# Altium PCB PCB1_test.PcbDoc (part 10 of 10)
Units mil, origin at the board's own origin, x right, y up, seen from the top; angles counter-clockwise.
Board outline 6690 x 6690 mil, 6 copper layers (Layer 1 - Top Layer, Layer 2 - GND, Layer 3 - PWR, Layer 4 - Signal, Layer 5 - GND, Layer 6 - Bottom Layer), stack 80.244 mil thick; 821 components, 458 nets, 3752 pads, 1525 vias.
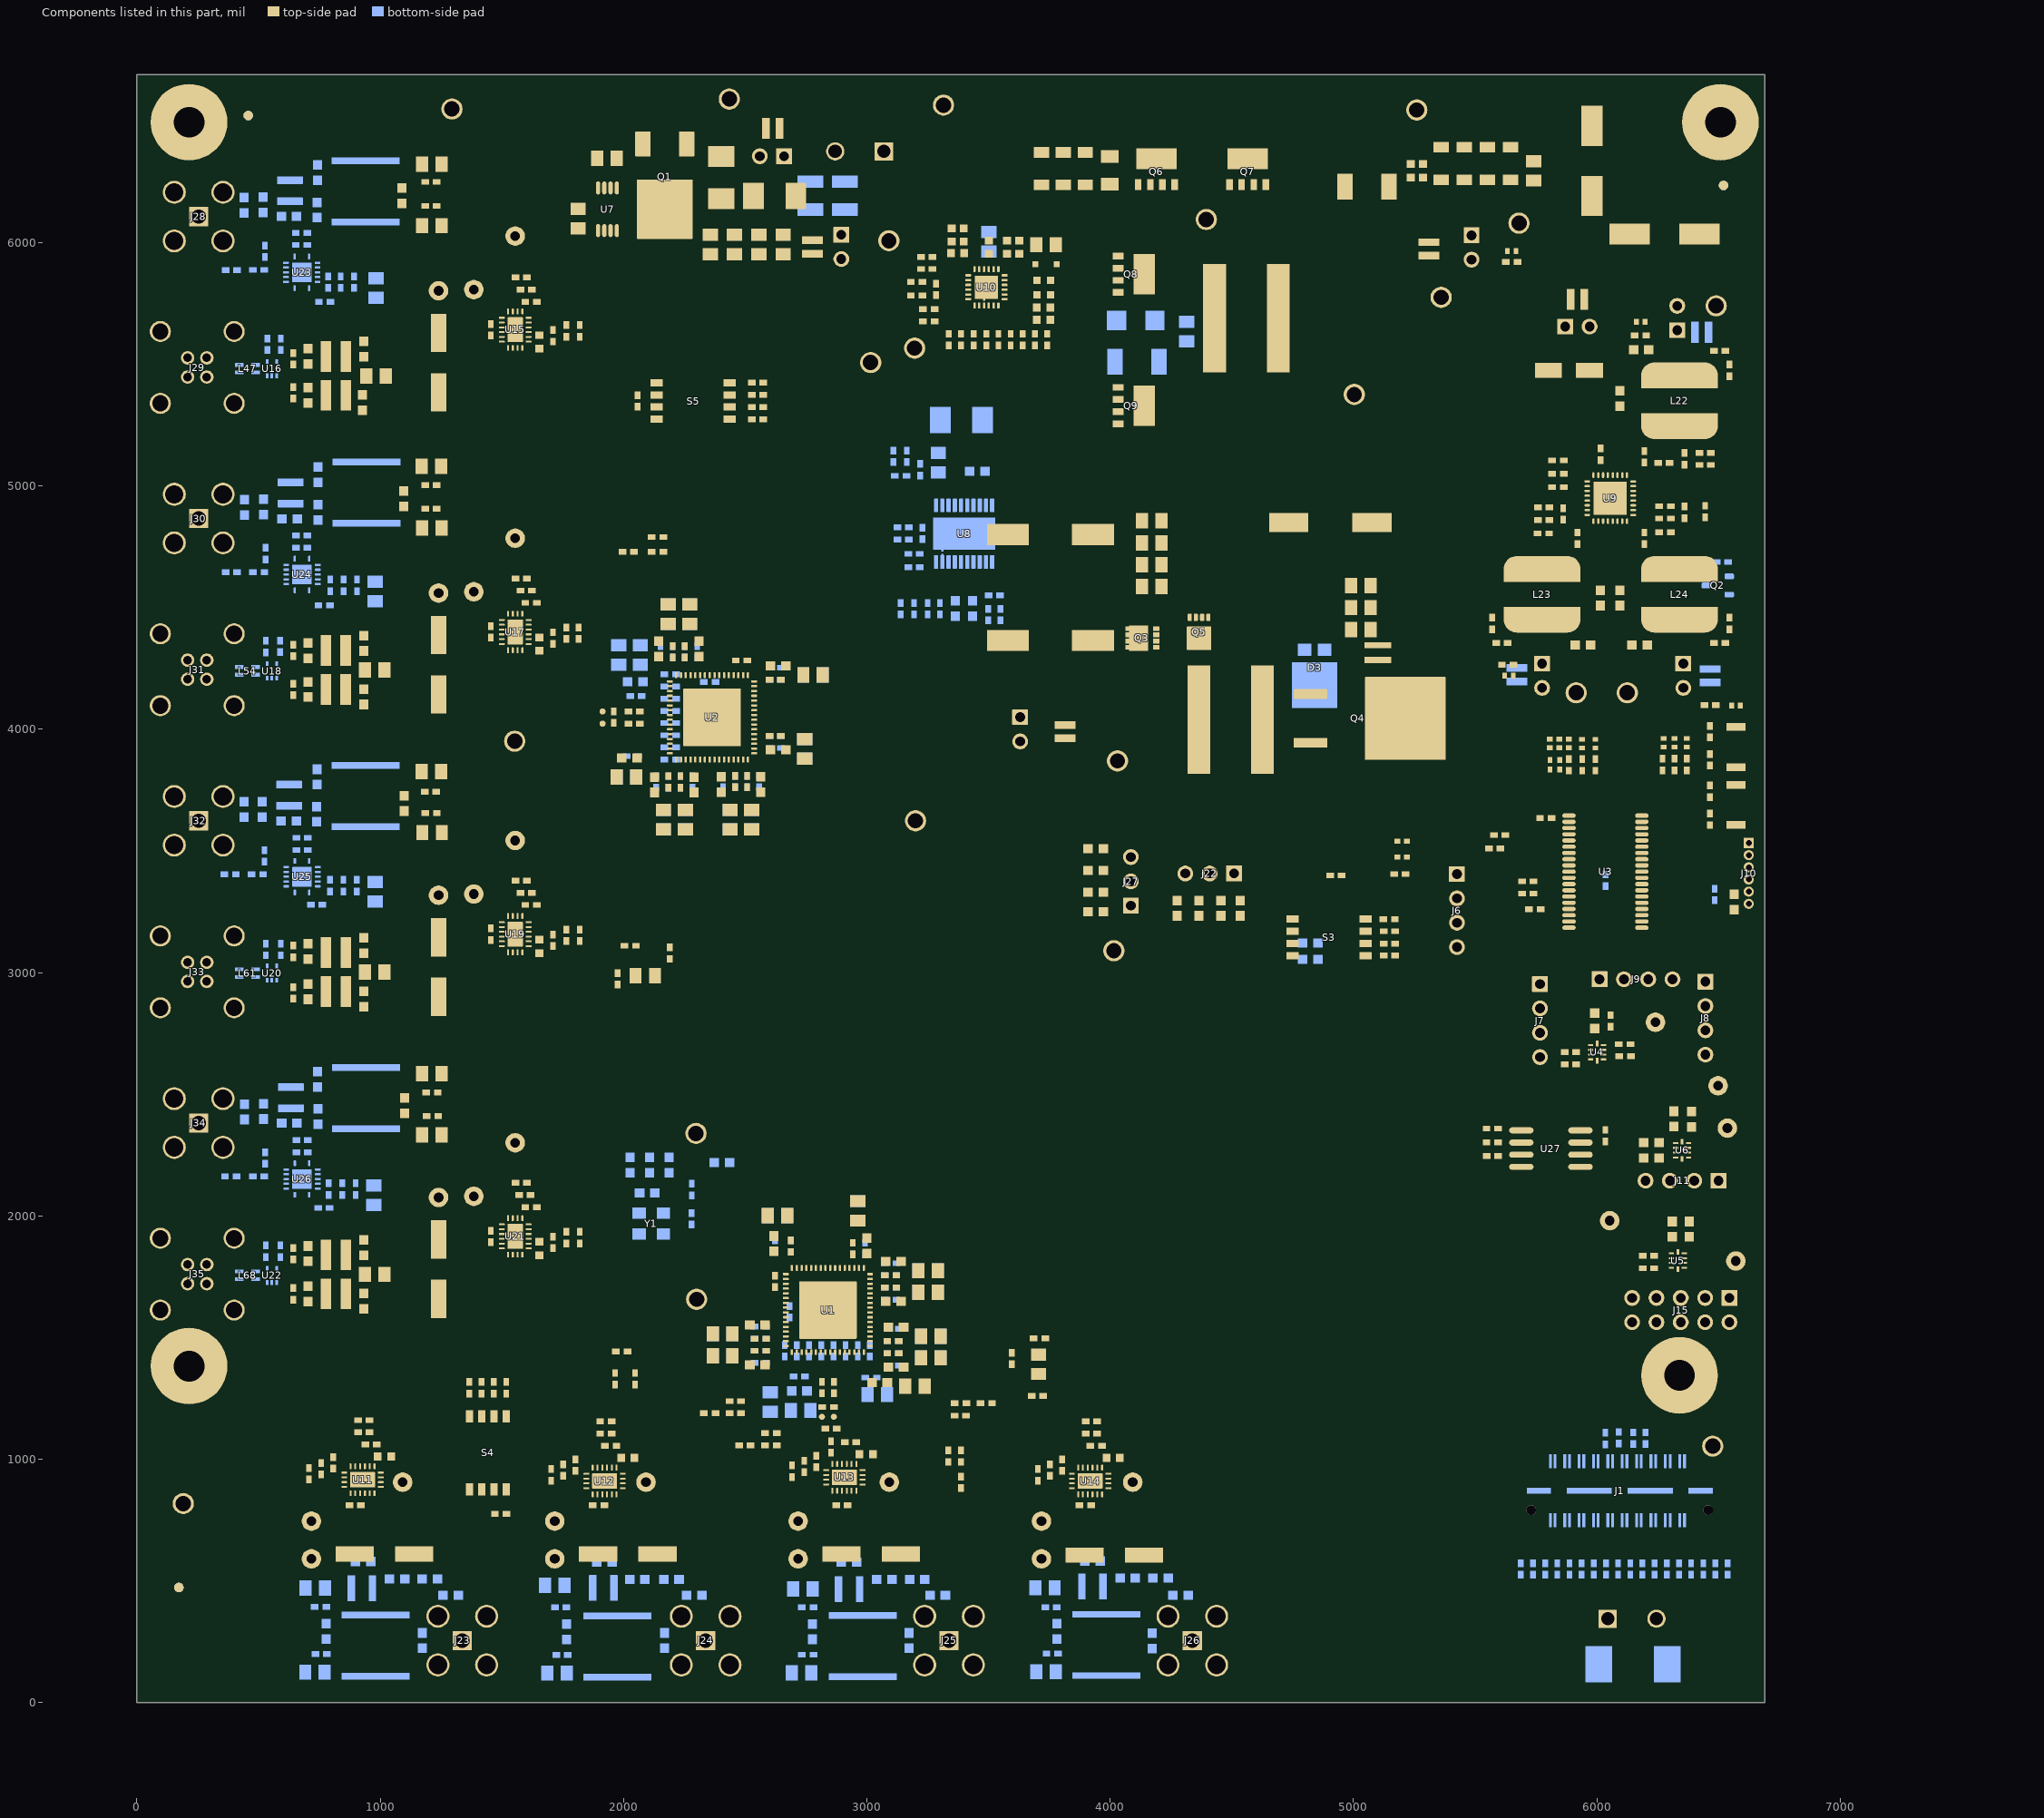
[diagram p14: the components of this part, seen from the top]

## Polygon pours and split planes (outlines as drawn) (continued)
NetR32_1 on Layer 6 - Bottom Layer "LAYER_6_-_BOTTOM_LAYER_NETR32_1_P303" (solid, remove dead copper, pour order 265): 2102.79,2069.09 2102.79,2139.09 2007.79,2139.09 2007.79,2199.09 2212.79,2199.09 2212.79,2139.09 2152.79,2139.09 2152.79,2069.09
AGND2 on Layer 6 - Bottom Layer "LAYER_6_-_BOTTOM_LAYER_AGND2_P251" (solid, remove dead copper, pour order 244): 3216,5179.48 3038.84,5179.48 3038.84,4472.24 3270.5,4472.24 3270.5,4734.48 3216,4734.48
GND on Layer 6 - Bottom Layer "LAYER_6_-_BOTTOM_LAYER_GND_P321" (solid, remove dead copper, pour order 274): 2654.09,1799.33 2654.09,1427.28 3026.14,1427.28 3026.14,1799.33
GND on Layer 6 - Bottom Layer "LAYER_6_-_BOTTOM_LAYER_GND_P323" (solid, remove dead copper, pour order 275): 2178.22,4233.86 2178.22,3861.81 2550.27,3861.81 2550.27,4233.86
GND on Layer 6 - Bottom Layer "LAYER_6_-_BOTTOM_LAYER_GND_P122" (solid, remove dead copper, pour order 195): 50,3787 50,3462 50,3352 400,3352 400,3787
GND on Layer 6 - Bottom Layer "LAYER_6_-_BOTTOM_LAYER_GND_P120" (solid, remove dead copper, pour order 194): 50,5029 50,4704 50,4594 400,4594 400,5029
GND on Layer 6 - Bottom Layer "LAYER_6_-_BOTTOM_LAYER_GND_P116" (solid, remove dead copper, pour order 193): 50,6270 50,5945 50,5835 400,5835 400,6270
GND on Layer 6 - Bottom Layer "Top Layer-No Net 1" (solid, remove dead copper, pour order 385): 31,35 4529.51,35 ccw(c4529.51,55.49) 4544,41 cw(c4558.49,55.49) 4538,55.49 4538,490.58 ccw(c4438,490.58) 4508.71,561.29 4103,967 ccw(c4074.03,938.03) 4074.03,979 765.42,979 ccw(c765.42,879) 694.71,949.71 31,286
5V on Layer 3 - PWR "LAYER_3_-_PWR_5V_P247" (solid, remove dead copper, pour order 242): 5920,5660 5920,4720 4780,4720 4780,3125 3825,3125 3825,3620 3825,4990 3825,5555 3825,5640 5810,5640 5810,5715 5920,5715
1V8 on Layer 3 - PWR "LAYER_3_-_PWR_1V8_P195" (solid, remove dead copper, pour order 219): 5485,61 5485,2325 5155,2325 5155,3430 5392,3667 5720,3975 5995,3975 5995,4230 4855,4230 4855,3020 3695,3020 3695,4445 2705,4445 2705,5535 1945,5535 1945,61
3V3 on Layer 3 - PWR "LAYER_3_-_PWR_3V3_P094" (solid, remove dead copper, pour order 183): 62,6629 62,60 1908,60 1908,5675 6040,5675 6420,5675 6420,5580 6420,4230 6040,4230 6040,3850 5225,3850 5225,2350 5575,2350 5575,20 6630,20 6630,6629
GND on Layer 5 - GND "LAYER_5_-_GND_GND_P265" (solid, remove dead copper, pour order 249): 6670.2,6670.5 20.2,6670.5 20.2,20.5 6670.2,20.5

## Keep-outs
Keep-Out Layer:
  text ".Layer_Name" at -883,-1308.49 h60

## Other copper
Layer 1 - Top Layer:
  rectangle net GND: 6335.69,1773.33 6369.69,1792.33
  region net GND: 1465,6670 1815,6670 1815,6370 1465,6370
  region net GND: 20,20 6670,20 6670,6670 20,6670 20,52.38 50,52.38 50,6640 6640,6640 6640,3582.23 6655,3582.23 6655,3240 6640,3240 6640,52.38 20,52.38
  text ".Layer_Name" at -883,-1308.49 h60
Layer 2 - GND:
  region net SW: 4075,5965 4075,5420 4255,5420 4255,5965
  pour cut-out: 2612,1121 2612,1093 2647,1093 2647,1121
  pour cut-out: 2565,1121 2565,1093 2599.5,1093 2599.5,1121
  pour cut-out: 2565,1071 2565,1043 2599.5,1043 2599.5,1071
  pour cut-out: 2612,1071 2612,1043 2647,1043 2647,1071
  pour cut-out: 2419,1253 2419,1225 2453.5,1225 2453.5,1253
  pour cut-out: 2466,1253 2466,1225 2501,1225 2501,1253
  pour cut-out: 2419,1204 2419,1176 2453.5,1176 2453.5,1204
  pour cut-out: 2466,1204 2466,1176 2501,1176 2501,1204
  pour cut-out: 3344,1244 3344,1216 3378.5,1216 3378.5,1244
  pour cut-out: 3391,1244 3391,1216 3426,1216 3426,1244
  pour cut-out: 3343,1193 3343,1165 3377.5,1165 3377.5,1193
  pour cut-out: 3390,1193 3390,1165 3425,1165 3425,1193
  pour cut-out: 3373,1018.75 3401,1018.75 3401,1053.25 3373,1053.25
  pour cut-out: 3373,971.5 3401,971.5 3401,1006.5 3373,1006.5
  pour cut-out: 3321,971.5 3349,971.5 3349,1006.5 3321,1006.5
  pour cut-out: 3321,1018.75 3349,1018.75 3349,1053.25 3321,1053.25
  text ".Layer_Name" at -883,-1308.49 h60
Layer 3 - PWR:
  text ".Layer_Name" at -883,-1308.49 h60
Layer 4 - Signal:
  text ".Layer_Name" at -883,-1308.49 h60
Layer 5 - GND:
  pour cut-out: 1298,463 1298,419 1344,419 1344,463
  pour cut-out: 2300,464 2300,420 2346,420 2346,464
  pour cut-out: 3299,463 3299,419 3345,419 3345,463
  pour cut-out: 4297,464 4297,420 4343,420 4343,464
  pour cut-out: 419,2419 419,2375 465,2375 465,2419
  pour cut-out: 418,3661 418,3617 464,3617 464,3661
  pour cut-out: 419,4902 419,4858 465,4858 465,4902
  pour cut-out: 417,6144 417,6100 463,6100 463,6144
  pour cut-out: 505,2177 505,2147 542,2147 542,2177
  pour cut-out: 458,2177 458,2147 495,2147 495,2177
  pour cut-out: 453,3419 453,3389 490,3389 490,3419
  pour cut-out: 500,3419 500,3389 537,3389 537,3419
  pour cut-out: 459,4661 459,4631 496,4631 496,4661
  pour cut-out: 506,4661 506,4631 543,4631 543,4661
  pour cut-out: 458,5903 458,5873 495,5873 495,5903
  pour cut-out: 505,5903 505,5873 542,5873 542,5903
  pour cut-out: 511,5922 541,5922 541,5959 511,5959
  pour cut-out: 511,5969.5 541,5969.5 541,6006.5 511,6006.5
  pour cut-out: 514,4727.5 544,4727.5 544,4764.5 514,4764.5
  pour cut-out: 514,4680 544,4680 544,4717 514,4717
  pour cut-out: 509,3485.5 539,3485.5 539,3522.5 509,3522.5
  pour cut-out: 509,3438 539,3438 539,3475 509,3475
  pour cut-out: 513,2243.5 543,2243.5 543,2280.5 513,2280.5
  pour cut-out: 513,2196 543,2196 543,2233 513,2233
  text ".Layer_Name" at -883,-1308.49 h60
Layer 6 - Bottom Layer:
  rectangle net NetC161_1: 5627,4235 5815,4306
  rectangle net 1V8: 5627,4095 5971.38,4214
  rectangle net 1V1: 6308,4137.61 6509,4209
  rectangle net NetC165_1: 6312,4230 6509,4309
  rectangle net 3V3: 6442,5586 6552,5790
  rectangle net NetC156_1: 6297,5568 6422,5676
  rectangle net VEVM_12v0: 6202.26,76.34 6348.95,382.25
  region net GND: 1465,6670 1815,6670 1815,6370 1465,6370
  region net GND: 20,20 6670,20 6670,6670 20,6670 20,50 50,50 50,6640 6640,6640 6640,3582.23 6655,3582.23 6655,3240 6640,3240 6640,50 6655,50 20,50
  text ".Layer_Name" at -883,-1308.49 h60

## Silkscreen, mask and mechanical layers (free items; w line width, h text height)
Top Overlay:
  lines w10: 1930,5953.23 1930,5739.31 2305,5739.31 2305,5740 2930,5740 ; 3605,6685 3605,6480 3260,6480 3260,6100 3085,6100 2980,6100 2980,5740 2930,5740 ; 4734,97.67 5556,97.67 ; 4736,99.67 4736,956.54 ; 4736,960.54 5557.13,960.54 ; 5520,5220 3840,5220 3840,5375 2935,5375 ; 5560,101.67 5560,957.67 ; 6635,4064 6006,4064 5833,4064 5833,4065 5520,4065 ; 6637,5957.17 6465,5957.17 6465,5840 5520,5840 5520,4065 ; 2930,5740 2935,5740 2935,5375 ; 2935,5375 2935,4270 3445,4270 3445,4120 3445,3750 4165,3750 5520,3750 5520,4065
  text "GND" at 1822,6588 h72.83 r270
  text "V_bat" at 2195,6518 h72.83
  text "GND" at 5043,6500 h72.83
  text "GND" at 3401,6489 h72.83
  text "GND" at 1077,6478 h72.83
  text "Battery / Input" at 1950,6470 h72.83
  text "Coax" at 350.39,6344.49 h72.83
  text "Radar / 0" at 50,5915 h72.83 r270
  text "3V3" at 6505,5878 h72.83
  text "HSD" at 340,5795 h72.83
  text "5V" at 5161,5697 h72.83
  text "3V3, 1V8, / 1V1 PMIC" at 5545,5666.34 h72.83
  text "GND" at 4943,5541 h72.83
  text "5V Buck / Converter" at 5187.99,5247.05 h72.83
  text "12 Boost / Converter" at 5191.28,5082 h72.83
  text "Coax" at 135,5055 h72.83
  text "Radar / 1" at 50,4674 h72.83 r270
  text "HSD" at 295,4555 h72.83
  text "1V8" at 6045,4095 h72.83 r90
  text "GND" at 1485,4090 h72.83
  text "1V1" at 6300,4085 h72.83 r90
  text "12V" at 4114,3849 h72.83
  text "Coax" at 105,3835 h72.83
  text "GND" at 3121.18,3730 h72.83
  text "Radar" at 4020,3600 h72.83
  text "Camera" at 4300,3540 h72.83
  text "12V" at 4040,3535 h72.83
  text "12V" at 4260,3475 h72.83
  text "5V" at 4475,3475 h72.83
  text "Radar / 2" at 50,3432 h72.83 r270
  text "HSD" at 260,3310 h72.83
  text "5V" at 4050,3170 h72.83
  text "GND" at 3783,3046 h72.83
  text "ADAS Sensor Fusion rev3" at 3746,2694.88 h72.83
  text "Coax" at 105,2570 h72.83
  text "ext. CLK" at 2382.87,2295.28 h72.83
  text "Radar / 3" at 50,2190 h72.83 r270
  text "HSD" at 310,2080 h72.83
  text "GND" at 2238.19,1804.13 h72.83
  text "GND" at 6410.67,925.2 h72.83
  text "GND" at 124,691 h72.83
  text "Plug either the / Coax or HSD connector! / Never both!" at 4740,687.44 h72.83
  text "Carefully select operating  / voltages and the correct /  connector" at 4746,402.39 h72.83
  text "GND" at 5846,190 h60 r90
  text "For a detailed bring up / guide, refer to the board / documentation." at 4734,144.35 h72.83
  text "+12V" at 6494.18,140 h60 r90
  text "Cam 2" at 2970,60 h72.83
  text "Cam 0" at 965,55 h72.83
  text "Cam 1" at 1975,55 h72.83
  text "Cam 3" at 3970,55 h72.83
  text ".Layer_Name" at -883,-1308.49 h60
Bottom Overlay:
  rectangle: 4887.44,1715.95 5465,1860
  rectangle: 3670.28,2435 4045.7,2540
  text "ASSY  518520 REV" at 5102,2450.87 h60
  text "PWB   518521 REV C" at 5102,2300.87 h60
  text "LOGIC 518522 REV C" at 5102,2175.87 h60
  text "S/N" at 5710,1750 h60
  text ".Layer_Name" at -883,-1308.49 h60
Top Paste:
  text ".Layer_Name" at -883,-1308.49 h60
Bottom Paste:
  text ".Layer_Name" at -883,-1308.49 h60
Top Solder:
  text ".Layer_Name" at -883,-1308.49 h60
  text ".Layer_Name" at -883,-1308.49 h60
Bottom Solder:
  text ".Layer_Name" at -883,-1308.49 h60
Drill Guide:
  text ".Layer_Name" at -883,-1308.49 h60
M1 Board Outline:
  lines w10: 0,0 6693,0 6693,6693.1 0,6693.1 0,0
  text ".Layer_Name" at -883,-1308.49 h60
M2 Board Dimensions:
  rectangle: -1460,-725 -1335,-600
  rectangle: -1335,-850 -960,-725
  lines w7: -1460,-725 -460,-725 ; -1335,-850 -1335,-600 ; -1210,-850 -1210,-600 ; -960,-850 -960,-600 ; -710,-850 -710,-600 ; -1460,-850 -460,-850 -460,-600 -1460,-600 -1460,-850
  text ".Layer_Name" at -883,-1308.49 h60
M3 3D STEP Top:
  text ".Layer_Name" at -883,-1308.49 h60
M4 3D STEP Bottom:
  text ".Layer_Name" at -883,-1308.49 h60
M5 Assembly Top:
  lines w10: -1752,-1380.17 4848,-1380.17 ; -1752,-1176.83 4850,-1176.83 ; -1752,-973.5 -1752,-1583.5 2253,-1583.5 4850,-1583.5 4850,-973.5 -1751.5,-973.5 -1751.5,-1583.5 -176,-1583.5 ; 713,-1583.5 713,-973.5 ; 1980,-1176.83 1980,-973.5 ; 2820,-1176.83 2820,-973.5 ; 3442,-1590 3442,-1387.17
  text "COMPONENTS MARKED 'DNP' SHOULD NOT BE POPULATED." at -306.5,-768.5 h40
  text "ASSEMBLY VARIANT:" at -307,-884 h40
  text ".VariantName" at 729,-884 h40
  text "PCB VIEWED FROM TOP SIDE" at -1688.5,-1105.67 h60
  text "BOARD #:" at 788,-1105.67 h60
  text ".PRJ_Number" at 1333.5,-1105.67 h60
  text "REV:" at 2178,-1105.67 h60
  text ".PCB_Rev" at 2469.5,-1105.67 h60
  text "SVN REV:" at 3016,-1105.67 h60
  text ".VersionControl_RevNumber" at 3522,-1105.67 h60
  text "TID #:" at 788,-1309 h60
  text ".TID" at 1333.5,-1309 h60
  text "PLOT NAME =" at -1688.5,-1514.34 h60
  text ".plot_File_Name" at -883,-1514.34 h60
  text "GENERATED    :" at 790,-1514.34 h60
  text ".Print_Date" at 1659.5,-1514.34 h60
  text ".Print_Time" at 2388.5,-1514.34 h60
  text "TEXAS INSTRUMENTS" at 3653,-1514.34 h60
M6 Assembly Bottom:
  lines w10: -1752.5,-1177.33 4849.5,-1177.33 ; -1750.5,-1380.67 4849.5,-1380.67 ; -344.5,-1590.5 -344.5,-1387.67 ; 277.5,-1177.33 277.5,-974 ; 1117.5,-1177.33 1117.5,-974 ; 2384.5,-1584 2384.5,-974 ; 3273.5,-1584 4849,-1584 4849,-974 -1752.5,-974 -1752.5,-1584 844.5,-1584 4849.5,-1584 4849.5,-974
  text "COMPONENTS MARKED 'DNP' SHOULD NOT BE POPULATED." at 4642,-768 h40
  text ".VariantName" at 3598,-884 h40
  text "ASSEMBLY VARIANT:" at 4637,-884 h40
  text ".VersionControl_RevNumber" at -424.5,-1106.17 h60
  text "SVN REV:" at 81.5,-1106.17 h60
  text ".PCB_Rev" at 628,-1106.17 h60
  text "REV:" at 919.5,-1106.17 h60
  text ".PRJ_Number" at 1764,-1106.17 h60
  text "BOARD #:" at 2309.5,-1106.17 h60
  text "PCB VIEWED FROM BOTTOM SIDE" at 4786,-1106.17 h60
  text ".TID" at 1764,-1309.5 h60
  text "TID #:" at 2309.5,-1309.5 h60
  text "TEXAS INSTRUMENTS" at -555.5,-1514.84 h60
  text ".Print_Time" at 709,-1514.84 h60
  text ".Print_Date" at 1438,-1514.84 h60
  text "GENERATED    :" at 2307.5,-1514.84 h60
  text ".plot_File_Name" at 3980.5,-1514.84 h60
  text "PLOT NAME =" at 4786,-1514.84 h60
M9 Title Sheet:
  drawing of 57 lines, arcs and shapes, not listed
  text "1" at -720.16,7586.5 h70
  text "2" at 1775.5,7586.5 h70
  text "3" at 4264.84,7586.5 h70
  text "4" at 6771.51,7586.5 h70
  text "5" at 9270.5,7586.5 h70
  text "6" at 11775.5,7586.5 h70
  text "A" at -1876.5,6443.5 h70
  text "A" at 12923.5,6443.5 h70
  text "B" at -1876.5,4063.5 h70
  text "B" at 12923.5,4063.5 h70
  text "C" at -1876.5,1688.5 h70
  text "C" at 12923.5,1688.5 h70
  text "PROJECT TITLE:" at 9883.5,-172.5 h45
  text ".PRJ_Title" at 9933.5,-305.83 h70
  text "DESIGNED FOR:" at 9883.5,-473.5 h45
  text ".PRJ_Customer" at 9933.5,-613.5 h70
  text "D" at -1876.5,-681.5 h70
  text "D" at 12923.5,-681.5 h70
  text "FILE NAME:" at 9883.5,-773.5 h45
  text ".PCB_File_Name_No_Path" at 9933.5,-893.5 h70
  text "Texas Instruments (TI) and/or its licensors do not warrant the accuracy or completeness of this specification" at 4914,-1055.34 h45
  text "ENGINEER:" at 9883.5,-1063.5 h45
  text "LAYOUT BY:" at 11388.5,-1063.5 h45
  text "or any information contained therein. TI and/or its licensors do not warrant that this design will meet" at 4869.01,-1168 h45
  text ".PRJ_Engineer" at 9933.5,-1218.49 h70
  text ".PCB_Layout" at 11439,-1218.49 h70
  text "the specifications, will be suitable for your application or fit for any particular purpose, or will operate in" at 4869.01,-1280.67 h45
  text ".Layer_Name" at -883,-1308.49 h60
  text "ALTIUM DESIGNER VERSION:" at 11388.5,-1373.5 h45
  text "an implementation. TI and/or its licensors do not warrant that the design is production worthy. You should" at 4869.01,-1393.33 h45
  text "completely validate and test your design implementation to confirm the system functionality for your application." at 4914,-1506 h45
  text ".print_Scale" at 9933.5,-1506.83 h70
  text ".Application_BuildNumber" at 11439,-1506.83 h70
  text "1" at -720.16,-1713.5 h70
  text "2" at 1775.5,-1713.5 h70
  text "3" at 4264.84,-1713.5 h70
  text "4" at 6771.51,-1713.5 h70
  text "5" at 9270.5,-1713.5 h70
  text "6" at 11775.5,-1713.5 h70
M10 Fab Notes:
  drawing of 173 lines, arcs and shapes, not listed
  text "DESIGN INFORMATION" at 10918.02,5751 h60
  text "0.1" at 11316,5585 h60
  text "MIN. TRACK WIDTH:" at 10273.46,5571 h60
  text "mm" at 11524.46,5571 h60
  text "MIN. CLEARANCE:" at 10273.46,5439 h60
  text "mm" at 11524.46,5439 h60
  text "0.13" at 11295,5437 h60
  text "MIN. VIA PAD SIZE:" at 10273.46,5307 h60
  text "mm" at 11524.46,5307 h60
  text "0.5" at 11303,5304 h60
  text "0.05mm (2MIL)" at 10993.46,5169.29 h60
  text "MINIMUM ANNULAR RING" at 9944.23,5161 h60
  text "EXTERNAL" at 11676.46,5161 h60
  text "PER" at 10144.23,5043 h60
  text "IPC-D-275 CLASS 2 LEVEL C" at 10364.23,5043 h60
  text "5" at 11712,4932 h60
  text "3" at 12555,4932 h60
  text "MIL, HOLES" at 11852.46,4930.71 h60
  text "+/-" at 11460,4930 h60
  text "+/-" at 12314,4930 h60
  text "REGISTRATION TOLERANCES:" at 9944.23,4925 h60
  text "METAL" at 11144,4925 h60
  text "MIL" at 12669.46,4925 h60
  text "+/-" at 12314,4812 h60
  text "3" at 12553,4810 h60
  text "HOLE SIZE TOLERANCE (UNLESS OTHERWISE SPECIFIED):" at 9944.23,4807 h60
  text "MIL" at 12669.46,4807 h60
  text "MATERIAL:" at 9869.46,4597.54 h60
  text "FR-4 High Tg" at 10855.9,4457.21 h60
  text "FR-408" at 10290.46,4448.64 h60
  text "OTHER" at 11778.46,4448.64 h60
  text "X" at 10701,4445 h60
  text "62 MIL (1.6mm) +/-10%" at 10610.56,4285.92 h60
  text "82 MIL" at 12220,4284 h60
  text "THICKNESS:" at 9944.23,4281.64 h60
  text "OTHER" at 11895.46,4281.64 h60
  text "X" at 11771,4273 h60
  text "TOLERANCE:" at 9944.23,4123.64 h60
  text "X" at 10783.53,4123.64 h60
  text "ANSI IPC-6012 TYPE 3 CLASS 2" at 10970.48,4123.64 h60
  text "OTHER +/-" at 10970.46,3967.64 h60
  text "BOW & TWIST:" at 9944.23,3810.64 h60
  text "X" at 10783.53,3810.64 h60
  text "ANSI IPC-6012 TYPE 3 CLASS 2" at 10970.48,3810.64 h60
  text "OTHER +/-" at 10970.46,3652.13 h60
  text "DRILLING:" at 9869.46,3513.64 h60
  text "REFERENCE:" at 9944.23,3396.64 h60
  text "X" at 10592.46,3396.64 h60
  text "AS SHOWN" at 10779.46,3396.64 h60
  text "X" at 11493.46,3396.64 h60
  text "NC_DRILL FILES" at 11630.46,3396.64 h60
  text "PTH COPPER THICKNESS:" at 9944.23,3238.64 h60
  text "X" at 11074.46,3238.64 h60
  text "20-30 um" at 11211.46,3238.64 h60
  text "OTHER" at 11928.46,3238.64 h60
  text "BOARD FINISH:" at 9869.46,3079.64 h60
  text "SILKSCREEN:" at 10024.68,2961.64 h60
  text "X" at 10973.46,2961.64 h60
  text "TOP" at 11099.46,2961.64 h60
  text "X" at 11483.46,2961.64 h60
  text "BOTTOM" at 11610.46,2961.64 h60
  text "SILKSCREEN COLOR:" at 10024.68,2794.64 h60
  text "X" at 10972.42,2794.64 h60
  text "WHITE" at 11099.46,2794.64 h60
  text "OTHER" at 11610.46,2794.64 h60
  text "X" at 11103.42,2635.44 h60
  text "GREEN" at 11230.46,2635.44 h60
  text "OTHER" at 11848.46,2635.44 h60
  text "SOLDER RESIST COLOR:" at 10024.68,2624.64 h60
  text "X" at 11103.42,2465.44 h60
  text "MATTE" at 11230.46,2465.44 h60
  text "SEMI-GLOSS" at 11848,2464.8 h60
  text "IMMERSION GOLD (ENIG)" at 10930.46,2276.92 h60
  text "ENEPIG" at 12268,2273.64 h60
  text "SURFACE FINISH:" at 9869.46,2272.64 h60
  text "X" at 10743.51,2272.64 h60
  text "IMM. TIN/SILVER OR EQUIV" at 10199,2115.64 h60
  text "OTHER" at 11630.46,2115.64 h60
  text "ARRAY/PANEL:" at 9869.46,1936.64 h60
  text "CUT AND TRIM PER M1 BOARD OUTLINE" at 10930.46,1932.35 h60
  text "N.C. ROUTE" at 10930.46,1780.64 h60
  text "X" at 11609.46,1780.64 h60
  text "V. SCORE" at 11796.46,1780.64 h60
  text "CERTIFICATION:" at 9869.46,1643.64 h60
  text "MATERIALS AND WORKMANSHIP FOR ALL PCBS" at 10594.46,1643.64 h60
  text "TO MEET OR EXCEED THE REQUIREMENTS OF:" at 10594.46,1545.64 h60
  text "X" at 10220.96,1409.13 h60
  text "ANSI IPC-A-600F CLASS ->" at 10359.96,1409.13 h60
  text "X" at 11999.02,1409.13 h60
  text "2" at 12117.96,1409.14 h60
  text "1" at 11802.96,1407.64 h60
  text "3" at 12471.96,1407.64 h60
  text "X" at 11035.02,1249.64 h60
  text "RoHS" at 11171.96,1249.64 h60
  text "OTHER" at 11816.36,1249.64 h60
  text "PER ORDER" at 12213.42,1249.64 h60
  text "ALL BOARDS MUST MEET OR EXCEED UL94-V0 REQUIREMENTS." at 9897,1084 h60
  text "PCB MUST BEAR THE UL94V-0 UL REGISTERED MATERIAL ID NUMBER" at 9897,964 h60
  text "ADDITIONAL REQUIREMENTS:" at 9869.46,790.64 h60
  text "MICROSECTION:" at 9944.23,675.64 h60
  text "YES" at 10849.96,675.64 h60
  text "REQUIRED" at 11711.46,519.49 h60
  text "BARE BOARD ELEC. TEST:" at 9944.23,516.64 h60
  text "NONE" at 11249.96,516.64 h60
  text "X" at 11584.46,516.64 h60
  text "PER ORDER" at 12303.46,516.64 h60
  text ".Layer_Name" at -883,-1308.49 h60
M11 Gerber Information:
  lines w10: -1752,-1380.17 4848,-1380.17 ; -1752,-1176.83 4850,-1176.83 ; -1752,-973.5 -1752,-1583.5 2253,-1583.5 4850,-1583.5 4850,-973.5 -1751.5,-973.5 -1751.5,-1583.5 -176,-1583.5 ; 713,-1583.5 713,-973.5 ; 1980,-1176.83 1980,-973.5 ; 2820,-1176.83 2820,-973.5 ; 3442,-1590 3442,-1387.17
  text "ALL ARTWORK VIEWED FROM TOP SIDE" at -1688.5,-1105.67 h60
  text "BOARD #:" at 788,-1105.67 h60
  text ".PRJ_Number" at 1333.5,-1105.67 h60
  text "REV:" at 2178,-1105.67 h60
  text ".PCB_Rev" at 2469.5,-1105.67 h60
  text "SVN REV:" at 3016,-1105.67 h60
  text ".VersionControl_RevNumber" at 3522,-1105.67 h60
  text "LAYER NAME =" at -1688.5,-1308.49 h60
  text "TID #:" at 788,-1309 h60
  text ".TID" at 1333.5,-1309 h60
  text "PLOT NAME =" at -1688.5,-1514.34 h60
  text ".plot_File_Name" at -883,-1514.34 h60
  text "GENERATED    :" at 790,-1514.34 h60
  text ".Print_Date" at 1659.5,-1514.34 h60
  text ".Print_Time" at 2388.5,-1514.34 h60
  text "TEXAS INSTRUMENTS" at 3653,-1514.34 h60
M12 Stackup:
  drawing of 399 lines, arcs and shapes, not listed
  text "Layer" at 6807.67,7395.84 h60
  text "Name" at 7217.58,7395.84 h60
  text "Material" at 8627.17,7395.84 h60
  text "Thickness" at 9486.94,7395.84 h60
  text "Constant" at 10136.77,7395.84 h60
  text "Board Layer Stack" at 10706.63,7395.84 h60
  text "1" at 6807.67,7275.84 h60
  text "Top Overlay" at 7217.58,7275.84 h60
  text "2" at 6807.67,7155.84 h60
  text "Top Solder" at 7217.58,7155.84 h60
  text "Solder Resist" at 8627.17,7155.84 h60
  text "0.50mil" at 9486.94,7155.84 h60
  text "3.5" at 10136.77,7155.84 h60
  text "3" at 6807.67,7035.84 h60
  text "Layer 1 - Top Layer" at 7217.58,7035.84 h60
  text "Copper" at 8627.17,7035.84 h60
  text "1.70mil" at 9486.94,7035.84 h60
  text "4" at 6807.67,6915.84 h60
  text "Dielectric1" at 7217.58,6915.84 h60
  text "370HR" at 8627.17,6915.84 h60
  text "4.06mil" at 9486.94,6915.84 h60
  text "4.2" at 10136.77,6915.84 h60
  text "5" at 6807.67,6795.84 h60
  text "Layer 2 - GND" at 7217.58,6795.84 h60
  text "Copper" at 8627.17,6795.84 h60
  text "1.18mil" at 9486.94,6795.84 h60
  text "6" at 6807.67,6675.84 h60
  text "Dielectric2" at 7217.58,6675.84 h60
  text "370HR" at 8627.17,6675.84 h60
  text "27.95mil" at 9486.94,6675.84 h60
  text "4.2" at 10136.77,6675.84 h60
  text "7" at 6807.67,6555.84 h60
  text "Layer 3 - PWR" at 7217.58,6555.84 h60
  text "Copper" at 8627.17,6555.84 h60
  text "1.18mil" at 9486.94,6555.84 h60
  text "8" at 6807.67,6435.84 h60
  text "Dielectric3" at 7217.58,6435.84 h60
  text "370HR" at 8627.17,6435.84 h60
  text "8.11mil" at 9486.94,6435.84 h60
  text "4.2" at 10136.77,6435.84 h60
  text "9" at 6807.67,6315.84 h60
  text "Layer 4 - Signal" at 7217.58,6315.84 h60
  text "Copper" at 8627.17,6315.84 h60
  text "1.18mil" at 9486.94,6315.84 h60
  text "10" at 6807.67,6195.84 h60
  text "Dielectric4" at 7217.58,6195.84 h60
  text "370HR" at 8627.17,6195.84 h60
  text "27.95mil" at 9486.94,6195.84 h60
  text "4.2" at 10136.77,6195.84 h60
  text "11" at 6807.67,6075.84 h60
  text "Layer 5 - GND" at 7217.58,6075.84 h60
  text "Copper" at 8627.17,6075.84 h60
  text "1.18mil" at 9486.94,6075.84 h60
  text "12" at 6807.67,5955.84 h60
  text "Dielectric5" at 7217.58,5955.84 h60
  text "370HR" at 8627.17,5955.84 h60
  text "4.06mil" at 9486.94,5955.84 h60
  text "4.2" at 10136.77,5955.84 h60
  text "13" at 6807.67,5835.84 h60
  text "Layer 6 - Bottom Layer" at 7217.58,5835.84 h60
  text "Copper" at 8627.17,5835.84 h60
  text "1.70mil" at 9486.94,5835.84 h60
  text "14" at 6807.67,5715.84 h60
  text "Bottom Solder" at 7217.58,5715.84 h60
  text "Solder Resist" at 8627.17,5715.84 h60
  text "0.50mil" at 9486.94,5715.84 h60
  text "3.5" at 10136.77,5715.84 h60
  text "15" at 6807.67,5595.84 h60
  text "Bottom Overlay" at 7217.58,5595.84 h60
  text ".Layer_Name" at -883,-1308.49 h60
M13 Component Bodies Top:
  text ".Layer_Name" at -883,-1308.49 h60
M14 Component Bodies Bottom:
  text ".Layer_Name" at -883,-1308.49 h60
M15 Courtyards Top:
  text ".Layer_Name" at -883,-1308.49 h60
M16 Courtyards Bottom:
  text ".Layer_Name" at -883,-1308.49 h60
Drill Drawing:
  circle w10: c6980.82,85.17 r20
  circle w10: c6980.82,85.17 r33.33
  circle w10: c6980.82,-214.83 r33.33
  lines w10: 6947.48,-698.16 7014.15,-698.16 7014.15,-631.49 6947.48,-631.49 6947.48,-698.16 ; 6947.48,-548.16 6980.82,-531.49 7014.15,-548.16 6997.48,-514.83 7014.15,-481.49 6980.82,-498.16 6947.48,-481.49 6964.15,-514.83 6947.48,-548.16 ; 6947.48,-381.49 6964.15,-381.49 6964.15,-398.16 6997.48,-398.16 6997.48,-381.49 7014.15,-381.49 7014.15,-348.16 6997.48,-348.16 6997.48,-331.49 6964.15,-331.49 6964.15,-348.16 6947.48,-348.16 6947.48,-381.49 ; 6947.48,-81.49 6964.15,-81.49 6980.82,-98.16 6997.48,-81.49 7014.15,-81.49 6997.48,-64.83 7014.15,-48.16 6997.48,-48.16 6980.82,-31.49 6964.15,-48.16 6947.48,-48.16 6964.15,-64.83 6947.48,-81.49 ; 6947.48,201.84 7014.15,201.84 7014.15,268.51 6947.48,268.51 6947.48,201.84 ; 6947.48,418.51 7014.15,418.51 6980.82,351.84 6947.48,418.51 ; 6947.48,501.84 6947.48,518.51 6964.15,535.17 6947.48,551.84 6947.48,568.51 6964.15,568.51 6980.82,551.84 6997.48,568.51 7014.15,568.51 7014.15,551.84 6997.48,535.17 7014.15,518.51 7014.15,501.84 6997.48,501.84 6980.82,518.51 6964.15,501.84 6947.48,501.84 ; 6947.48,668.51 6964.15,668.51 6980.82,651.84 6997.48,668.51 7014.15,668.51 6997.48,685.17 7014.15,701.84 6997.48,701.84 6980.82,718.51 6964.15,701.84 6947.48,701.84 6964.15,685.17 6947.48,668.51 ; 6947.48,835.17 6980.82,801.84 7014.15,835.17 6980.82,868.51 6947.48,835.17 ; 6947.48,968.51 6964.15,968.51 6964.15,951.84 6997.48,951.84 6997.48,968.51 7014.15,968.51 7014.15,1001.84 6997.48,1001.84 6997.48,1018.51 6964.15,1018.51 6964.15,1001.84 6947.48,1001.84 6947.48,968.51 ; 6947.48,1101.84 6980.82,1118.51 7014.15,1101.84 6997.48,1135.17 7014.15,1168.51 6980.82,1151.84 6947.48,1168.51 6964.15,1135.17 6947.48,1101.84 ; 6947.48,1318.51 7014.15,1318.51 6980.82,1251.84 6947.48,1318.51 ; 6960.82,215.17 7000.82,215.17 7000.82,255.17 6960.82,255.17 6960.82,215.17 ; 6960.82,675.17 6970.82,675.17 6980.82,665.17 6990.82,675.17 7000.82,675.17 6990.82,685.17 7000.82,695.17 6990.82,695.17 6980.82,705.17 6970.82,695.17 6960.82,695.17 6970.82,685.17 6960.82,675.17 ; 6960.82,975.17 6970.82,975.17 6970.82,965.17 6990.82,965.17 6990.82,975.17 7000.82,975.17 7000.82,995.17 6990.82,995.17 6990.82,1005.17 6970.82,1005.17 6970.82,995.17 6960.82,995.17 6960.82,975.17 ; 6960.82,1115.17 6980.82,1125.17 7000.82,1115.17 6990.82,1135.17 7000.82,1155.17 6980.82,1145.17 6960.82,1155.17 6970.82,1135.17 6960.82,1115.17 ; 6960.82,1305.17 7000.82,1305.17 6980.82,1265.17 6960.82,1305.17
  lines w15: 6887.69,-743.16 9778.93,-743.16 ; 6887.69,1356.84 9778.93,1356.84 ; 7438.57,-893.16 7438.57,1506.84 ; 8078.4,-893.16 8078.4,1506.84 ; 9228.06,-893.16 9228.06,1506.84 ; 6887.69,-893.16 9778.93,-893.16 9778.93,1506.84 6887.69,1506.84 6887.69,-893.16
  text "Symbol" at 6977.69,1401.84 h72
  text "Count" at 7483.57,1401.84 h72
  text "Hole Size" at 8123.4,1401.84 h72
  text "Plated" at 9273.06,1401.84 h72
  text "497" at 7483.57,1251.84 h60
  text "7.87mil (0.200mm)" at 8123.4,1251.84 h60
  text "PTH" at 9273.06,1251.84 h60
  text "854" at 7483.57,1101.84 h60
  text "10.00mil (0.254mm)" at 8123.4,1101.84 h60
  text "PTH" at 9273.06,1101.84 h60
  text "73" at 7483.57,951.84 h60
  text "15.00mil (0.381mm)" at 8123.4,951.84 h60
  text "PTH" at 9273.06,951.84 h60
  text "6" at 7483.57,801.84 h60
  text "24.00mil (0.610mm)" at 8123.4,801.84 h60
  text "PTH" at 9273.06,801.84 h60
  text "101" at 7483.57,651.84 h60
  text "28.00mil (0.711mm)" at 8123.4,651.84 h60
  text "PTH" at 9273.06,651.84 h60
  text "16" at 7483.57,501.84 h60
  text "35.43mil (0.900mm)" at 8123.4,501.84 h60
  text "PTH" at 9273.06,501.84 h60
  text "81" at 7483.57,351.84 h60
  text "40.00mil (1.016mm)" at 8123.4,351.84 h60
  text "PTH" at 9273.06,351.84 h60
  text "2" at 7483.57,201.84 h60
  text "40.16mil (1.020mm)" at 8123.4,201.84 h60
  text "NPTH" at 9273.06,201.84 h60
  text "4" at 7483.57,51.84 h60
  text "55.12mil (1.400mm)" at 8123.4,51.84 h60
  text "PTH" at 9273.06,51.84 h60
  text "8" at 7483.57,-98.16 h60
  text "59.06mil (1.500mm)" at 8123.4,-98.16 h60
  text "PTH" at 9273.06,-98.16 h60
  text "22" at 7483.57,-248.16 h60
  text "63.00mil (1.600mm)" at 8123.4,-248.16 h60
  text "PTH" at 9273.06,-248.16 h60
  text "16" at 7483.57,-398.16 h60
  text "66.93mil (1.700mm)" at 8123.4,-398.16 h60
  text "PTH" at 9273.06,-398.16 h60
  text "32" at 7483.57,-548.16 h60
  text "74.80mil (1.900mm)" at 8123.4,-548.16 h60
  text "PTH" at 9273.06,-548.16 h60
  text "4" at 7483.57,-698.16 h60
  text "125.98mil (3.200mm)" at 8123.4,-698.16 h60
  text "PTH" at 9273.06,-698.16 h60
  text "1716 Total" at 7483.57,-848.16 h60
  text ".Layer_Name" at -883,-1308.49 h60
Mechanical 17:
  text ".Layer_Name" at -883,-1308.49 h60
Mechanical 18:
  text ".Layer_Name" at -883,-1308.49 h60
Mechanical 19:
  text ".Layer_Name" at -883,-1308.49 h60
M20 DXFIN MATE:
  drawing of 6324 lines, arcs and shapes, not listed
M31 TMP LAYOUT NOTES:
  text "R128 - R131 routes have been moved from the top" at 4193,2289 h40
  text "to layer four in order to create a clear path to route to" at 4186,2242 h40
  text "J1. Once this scheme is approved U1 and U2 routes" at 4181,2191 h40
  text "will be completed with added tuning delays per" at 4176,2142 h40
  text "design rules." at 4175,2090 h40

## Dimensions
-1460,-850 to -460,-850 on M2 Board Dimensions
-840,-20 to -840,6670 on M2 Board Dimensions
1.91,-400 to 6691.91,-370 on M2 Board Dimensions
